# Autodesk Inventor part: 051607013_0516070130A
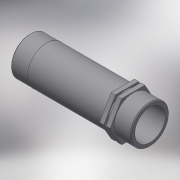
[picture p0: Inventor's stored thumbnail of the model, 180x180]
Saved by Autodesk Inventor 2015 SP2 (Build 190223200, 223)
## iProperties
Created: 2017-05
Part Number: 051607013_0516070130A
Material: Generic
Description: PLASSON RISER 1.1/4"-1.1/4"
Document SubType Name: Modeling
Designer: KIM
Mass: 20.3153 g
Surface Area: 184.457 cm^2
Volume: 20.3153 cm^3
Density: 1 g/cm^3
Appearance: Default
Author: KIM
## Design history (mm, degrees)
derived "051607.ipt"
feature "Solid1::051607.ipt"
tag "TaggingFeature1"
body "Solid1"
other parameters: "d1" = 41.91, "d2" = 46, "d3" = 33.528, "d5" = 21, "d6" = 5.25, "d8" = 1.05, "d12" = 0, "d13" = 2.625, "d15" = 21, "d17" = 0, "d18" = 41.91, "R_" = 41.91, "E_" = 46, "l_2" = 21, "R_1" = 41.91
